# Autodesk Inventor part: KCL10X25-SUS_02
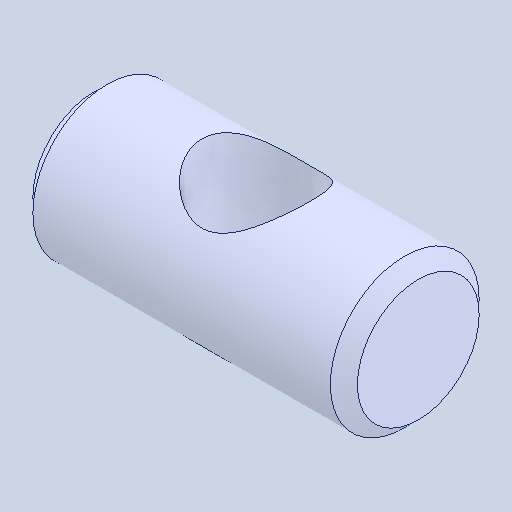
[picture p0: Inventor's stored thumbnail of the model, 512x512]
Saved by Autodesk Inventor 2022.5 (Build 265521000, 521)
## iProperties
Created: 2024-08
Part Number: KCL10X25-SUS_02
Material: 一般
Document SubType Name: Modeling
Designer: ImaoCorp
Density: 1 g/cm^3
Appearance: 既定
Author: ImaoCorp
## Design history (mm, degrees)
feature "KCL10X25-SUS_02"
node "ソリッド1"
